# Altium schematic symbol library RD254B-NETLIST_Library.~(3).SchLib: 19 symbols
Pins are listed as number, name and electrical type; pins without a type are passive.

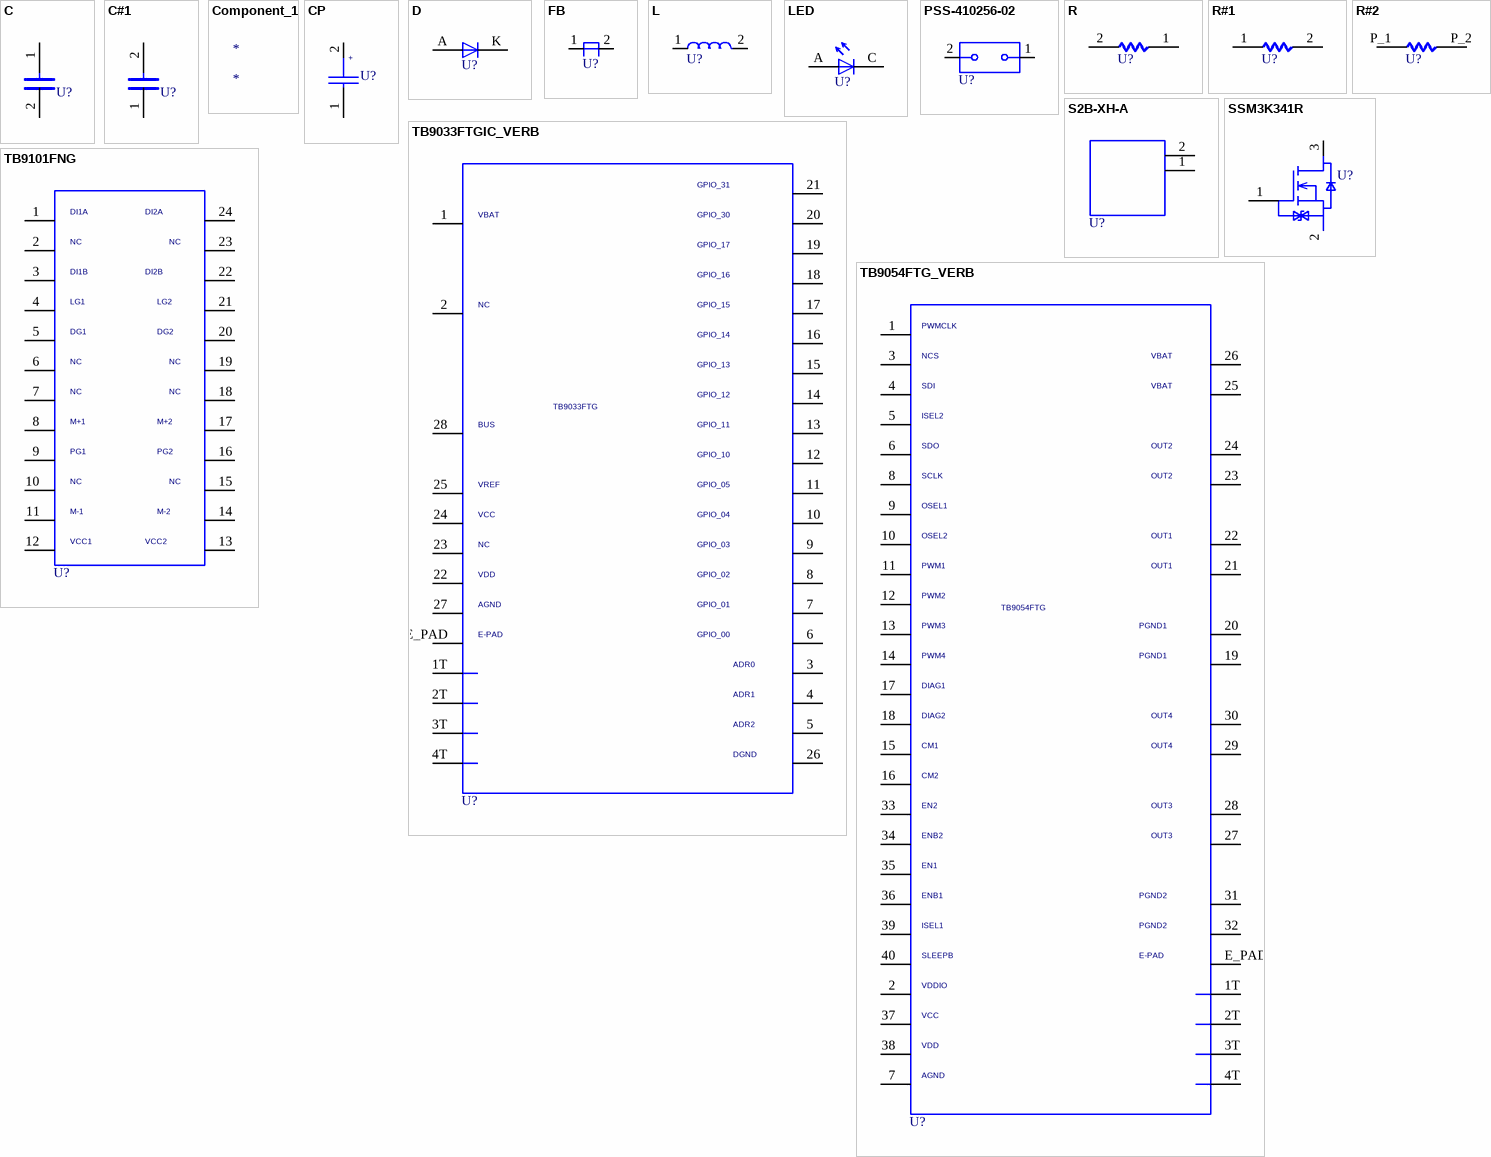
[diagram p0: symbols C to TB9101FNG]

## C
designator U?  (value not drawn)
OriginalSymbolOrigin: (2540,7620); Altium-Right: 20; Altium-Bottom: 10
pins: 1 2, 2 1

## C#1
designator U?, comment C  (value not drawn)
OriginalSymbolOrigin: (2540,7620); Altium-Right: 20; Altium-Bottom: 10
pins: 1, 2

## Component_1
designator *

## CP
designator U?  (value not drawn)
SAVEAREA0: -1450,-153,20294,13055; SAVECOUNT: 52; TIME: 15:02:55; UPDATEUSER: fukuda-y; UPDATETIME: 16:13:42; OriginalSymbolOrigin: (2540,10160); Altium-Right: 20
pins: 1, 2

## D
designator U?  (value not drawn)
SAVEAREA0: -225,-91,12804,7836; SAVECOUNT: 3; TIME: 14:49:55; UPDATEUSER: 19870035; UPDATETIME: 14:20:16; OriginalSymbolOrigin: (5080,5080); Altium-Right: 10; Altium-Bottom: 20
pins: A, K C

## FB
designator U?  (value not drawn)
SAVEAREA0: -63393,-16950,474261,314592; TIME: 14:30:25; UPDATEUSER: t5459927; UPDATETIME: 11:02:03; SAVECOUNT: 20; OriginalSymbolOrigin: (7620,7620); Altium-Right: 10
pins: 1, 2

## L
designator U?  (value not drawn)
OriginalSymbolOrigin: (2540,5080); Altium-Right: 30; Altium-Bottom: 20
pins: 1, 2

## LED
designator U?  (value not drawn)
SAVEAREA0: -6799,-183,19247,15664; TIME: 14:49:55; UPDATEUSER: fukuda-y; UPDATETIME: 13:54:07; SAVECOUNT: 4; OriginalSymbolOrigin: (5080,7620); Altium-Right: 10; Altium-Bottom: 30
pins: A, C

## PSS-410256-02
designator U?  (value not drawn)
SAVEAREA0: -63393,-16950,474261,314592; TIME: 14:30:25; UPDATEUSER: t5459927; UPDATETIME: 18:56:33; SAVECOUNT: 22; OriginalSymbolOrigin: (2540,5080); Altium-Right: 40; Altium-Bottom: 20
pins: 1 2, 2 1

## R
designator U?  (value not drawn)
OriginalSymbolOrigin: (5080,5080); Altium-Right: 20
pins: 1 2, 2 1

## R#1
designator U?, comment R  (value not drawn)
OriginalSymbolOrigin: (5080,5080); Altium-Right: 20
pins: 1, 2

## R#2
designator U?, comment R  (value not drawn)
OriginalSymbolOrigin: (5080,5080); Altium-Right: 20
pins: P_1 1, P_2 2

## S2B-XH-A
designator U?  (value not drawn)
SAVEAREA0: -63393,-16950,474261,314592; TIME: 14:30:25; UPDATEUSER: t5459927; UPDATETIME: 11:18:03; SAVECOUNT: 20; OriginalSymbolOrigin: (0,12700); Altium-Right: 50
pins: 1, 2

## SSM3K341R
designator U?  (value not drawn)
SAVEAREA0: -63393,-16950,474261,314592; TIME: 14:30:25; UPDATEUSER: t5459927; UPDATETIME: 12:01:19; SAVECOUNT: 22; OriginalSymbolOrigin: (5080,12700); Altium-Right: 40; Altium-Bottom: 50
pins: 1, 2, 3

## TB9033FTGIC_VERB
designator U?  VAL3: TB9033FTG  (hidden comment: TB9033FTGIC_VERB)
SAVEAREA0: -63393,-16950,474261,314592; TIME: 14:30:25; UPDATEUSER: t5459927; UPDATETIME: 17:47:26; SAVECOUNT: 27; OriginalSymbolOrigin: (5080,106680); Altium-Right: 220; Altium-Bottom: 420
pins: 1, 1T, 2, 2T, 3, 3T, 4, 4T, 5, 6, 7, 8, 9, 10, 11, 12, 13, 14, 15, 16, 17, 18, 19, 20, 21, 22, 23, 24, 25, 26, 27, 28, E_PAD

## TB9054FTG_VERB
designator U?  VAL3: TB9054FTG  (hidden comment: TB9054FTG_VERB)
SAVEAREA0: -63393,-16950,474261,314592; TIME: 14:30:25; UPDATEUSER: t5459927; UPDATETIME: 17:43:58; SAVECOUNT: 30; OriginalSymbolOrigin: (5080,137160); Altium-Right: 200; Altium-Bottom: 540
pins: 1, 1T, 2, 2T, 3, 3T, 4, 4T, 5, 6, 7, 8, 9, 10, 11, 12, 13, 14, 15, 16, 17, 18, 19, 20, 21, 22, 23, 24, 25, 26, 27, 28, 29, 30, 31, 32, 33, 34, 35, 36, 37, 38, 39, 40, E_PAD

## TB9101FNG
designator U?  (value not drawn)
SAVEAREA0: -63393,-16950,474261,314592; TIME: 14:30:25; UPDATEUSER: t5459927; UPDATETIME: 15:25:03; SAVECOUNT: 19; OriginalSymbolOrigin: (5080,63500); Altium-Right: 100; Altium-Bottom: 250
pins: 1, 2, 3, 4, 5, 6, 7, 8, 9, 10, 11, 12, 13, 14, 15, 16, 17, 18, 19, 20, 21, 22, 23, 24

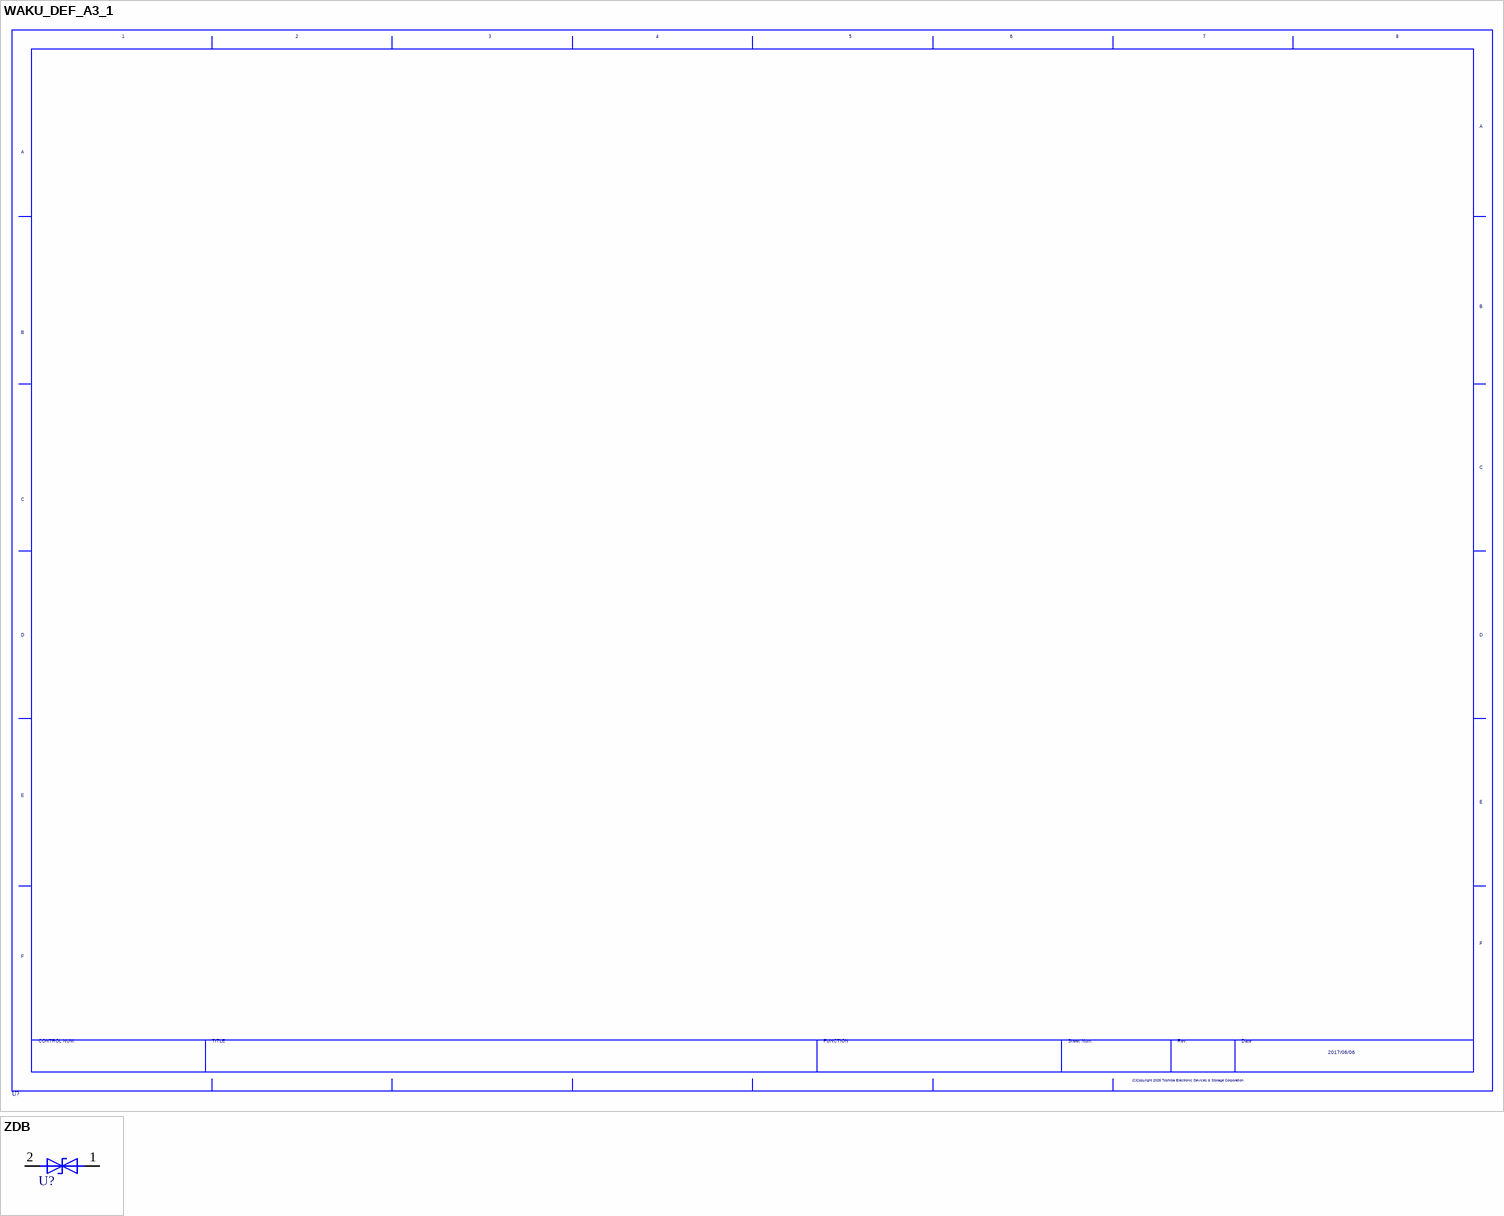
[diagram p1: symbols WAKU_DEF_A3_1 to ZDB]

## WAKU_DEF_A3_1
designator U?  DATE: 2017/06/06  (hidden comment: WAKU_DEF_A3_1)
PLOTTIME: HH:MM; SAVEAREA0: 96913,-567914,509243,-368858; TIME: 14:30:25; UPDATEUSER: t5459927; UPDATETIME: 11:07:19; SAVECOUNT: 23; ZONEOFFSETX: 36; ZONEOFFSETY: -24; OriginalSymbolOrigin: (12700,-12700); Altium-Right: 2300; Altium-Bottom: 1650

## ZDB
designator U?  (value not drawn)
SAVEAREA0: -4630,-153,17114,13055; TIME: 14:49:55; UPDATEUSER: fukuda-y; UPDATETIME: 08:22:19; SAVECOUNT: 6; OriginalSymbolOrigin: (2540,5080); Altium-Right: 30; Altium-Bottom: 20
pins: 1 2, 2 1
